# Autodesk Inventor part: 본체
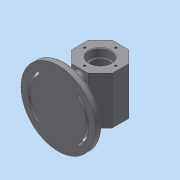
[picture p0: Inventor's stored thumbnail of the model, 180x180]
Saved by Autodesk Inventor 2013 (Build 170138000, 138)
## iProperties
Created: 2017-06
Part Number: 본체
Material: 일반
Document SubType Name: Modeling
Designer: dgall
Density: 1 g/cm^3
Author: dgall
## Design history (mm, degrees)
sketch "스케치1" dims "d0" = 60
  geometry: L1 (12.426, 30)-(30, 12.426); L2 (30, 12.426)-(30, -12.426); L3 (30, -12.426)-(12.426, -30); L4 (12.426, -30)-(-12.426, -30); L5 (-12.426, -30)-(-30, -12.426); L6 (-30, -12.426)-(-30, 12.426); L7 (-30, 12.426)-(-12.426, 30); L8 (-12.426, 30)-(12.426, 30); 4 further points
  constraints: 16 end point, 2 coincident, 2 vertical alignment, 1 midpoint, 19 other
extrude "돌출1" new body sketch "스케치1" stored distance "d1" = 70; taper "d2" = 0 deg
sketch "스케치2"
  geometry: L1 (30, -35)-(-30, -35) reference; L2 (-30, -35)-(-30, 35) reference; L3 (-30, 35)-(30, 35) reference; L4 (30, 35)-(30, -35) reference; L5 (0, -35)-(16, -35); L6 (16, -35)-(16, -23); L7 (16, -23)-(14, -23); L8 (14, -23)-(14, -20); L9 (14, -20)-(25, -20); L10 (25, -20)-(25, 20); L11 (25, 20)-(14, 20); L12 (14, 20)-(14, 23); L13 (14, 23)-(16, 23); L14 (16, 23)-(16, 35); L15 (16, 35)-(0, 35); L16 (0, 35)-(0, -35)
  constraints: 24 end point, 3 horizontal, 3 parallel, 3 perpendicular, 2 collinear, 2 midpoint, 2 point on line, 2 vertical alignment
  dimensions: "d6" = 12 distance of L5.end L6.end; "d7" = 40 distance of L9.end L10.end; "d9" = 12 distance of L13.end L14.end; "d10" = 32 diameter of L14 L16; "d11" = 50 diameter of L10 L16; "d12" = 28 diameter of L12 L16
revolve "회전1" sketch "스케치2" stored, may be unused: angle "d13" = 90 deg
node "작업 평면1"
sketch "스케치3"
  geometry: C1 r 55 at (0, 0); 1 further point
  constraints: 1 centre point, 1 coincident
  dimensions: "d15" = 110 diameter of C1
extrude "돌출2" join sketch "스케치3" distance "d16" = 10; taper "d17" = 0 deg
sketch "스케치4"
  geometry: L1 (-55, 0)-(0, 0); L2 (0, 0)-(-38.891, -38.891); L3 (-30.406, 30.406)-(0, 0); A1 r 55 centre (0, 0) between (-55, 0) and (-38.891, -38.891) reference; A2 r 43 centre (0, 0) between (-30.406, -30.406) and (-30.406, 30.406); A3 r 48 centre (0, 0) between (-33.941, 33.941) and (-33.941, -33.941); A4 r 38 centre (0, 0) between (-26.87, 26.87) and (-26.87, -26.87); A5 r 5 centre (-30.406, -30.406) between (-33.941, -33.941) and (-26.87, -26.87); A6 r 5 centre (-30.406, 30.406) between (-26.87, 26.87) and (-33.941, 33.941)
  constraints: 12 point on circle, 6 end point, 5 centre point, 4 coincident, 3 point on line, 1 horizontal
  dimensions: "d18" = 86 diameter of A2; "d19" = 96 diameter of A3; "d20" = 76 diameter of A4; "d21" = 45 deg angle of L1 L2; "d23" = 90 deg angle of L2 L3
extrude "돌출3" cut sketch "스케치4" distance "d24" = 3; taper "d25" = 0 deg
sketch "스케치5"
  geometry: A1 r 38 centre (0, 0) between (-26.87, 26.87) and (-26.87, -26.87) reference; A2 r 5 centre (-30.406, 30.406) between (-26.87, 26.87) and (-33.941, 33.941) reference; A3 r 48 centre (0, 0) between (-33.941, 33.941) and (-33.941, -33.941) reference; A4 r 5 centre (-30.406, -30.406) between (-33.941, -33.941) and (-26.87, -26.87) reference; A5 r 45 centre (0, 0) between (-31.82, 31.82) and (-31.82, -31.82); A6 r 2 centre (-30.406, 30.406) between (-28.991, 28.991) and (-31.82, 31.82); A7 r 41 centre (0, 0) between (-28.991, 28.991) and (-28.991, -28.991); A8 r 2 centre (-30.406, -30.406) between (-31.82, -31.82) and (-28.991, -28.991)
  constraints: 8 point on circle, 4 centre point, 3 other
  dimensions: "d26" = 3 radial gap between concentric circles of A3 A5
extrude "돌출4" cut sketch "스케치5" stored distance "d27" = 3; taper "d28" = 0 deg
sketch "스케치6"
  geometry: L1 (16, -35)-(16, -23) reference; L2 (16, -23)-(14, -23) reference; L3 (14, -23)-(14, -20) reference; L4 (14, -20)-(25, -20) reference; L5 (25, -20)-(25, 20) reference; L6 (25, 20)-(14, 20) reference; L7 (14, 20)-(14, 23) reference; L8 (14, 23)-(16, 23) reference; L9 (16, 23)-(16, 35) reference; L10 (16, 35)-(30, 35) reference; L11 (30, 35)-(30, -35) reference; L12 (30, -35)-(16, -35) reference; L13 (-16, -23)-(-16, -35) reference; L14 (-16, -35)-(-30, -35) reference; L15 (-30, -35)-(-30, 35) reference; L16 (-30, 35)-(-16, 35) reference; L17 (-16, 35)-(-16, 23) reference; L18 (-16, 23)-(-14, 23) reference; L19 (-14, 23)-(-14, 20) reference; L20 (-14, 20)-(-25, 20) reference; L21 (-25, 20)-(-25, -20) reference; L22 (-25, -20)-(-14, -20) reference; L23 (-14, -20)-(-14, -23) reference; L24 (-14, -23)-(-16, -23) reference; L25 (-62, 55)-(-52, 55) reference; L26 (-52, 55)-(-52, -55) reference; L27 (-52, -55)-(-62, -55) reference; L28 (-62, -55)-(-62, 55) reference; L29 (-30, 29)-(-52, 29); L30 (-30, -29)-(-52, -29); 1 further point
  constraints: 4 end point, 4 point on line, 2 perpendicular
  dimensions: "d29" = 58 distance between parallel lines of L30 L29; "d30" = 29 distance from line of L30 point (0, 0)
extrude "돌출5" join sketch "스케치6" stored distance "d31" = 10; taper "d32" = 0 deg
fillet "모깎기1" dims "d33" = 1
fillet "모깎기2" dims "d34" = 5
fillet "모깎기3" dims "d35" = 5
fillet "모깎기4" dims "d36" = 3
chamfer "모따기1" distance "d37" = 1; stored, may be unused: second distance "d38" = 2, angle "d39" = 45 deg
fillet "모깎기5" dims "d40" = 0.3
fillet "모깎기6" dims "d41" = 3
sketch "스케치7" dims "d42" = 46
  geometry: C1 r 17 at (0, 0) reference; 2 further points
  constraints: 2 vertical alignment, 1 coincident, 2 other
hole "구멍1" sketch "스케치7" at (0, 23) diameter "d43" = 3.242; stored, may be unused: countersink angle "d47" = 90 deg, drill point angle "d49" = 118 deg; dims "d44" = 8, "d45" = 4, "d46" = 2, "d48" = 10
sketch "스케치8"
  geometry: L1 (-24.024, 70)-(0, 70) reference; L2 (0, 0)-(-24.024, 0) reference; C1 r 8 at (-12.012, 35); 2 further points
  constraints: 1 centre point, 1 midpoint, 1 vertical alignment
  dimensions: "d53" = 35 distance from line of L2 C1.centre; "d54" = 16 diameter of C1
extrude "돌출6" join sketch "스케치8" distance "d55" = 7; taper "d56" = 0 deg
sketch "스케치9"
  geometry: C1 r 8 at (0, 0) reference
hole "구멍2" sketch "스케치9" at (0, 0) diameter "d57" = 8; stored, may be unused: countersink angle "d61" = 90 deg, drill point angle "d63" = 118 deg; dims "d58" = 8, "d59" = 4, "d60" = 2, "d62" = 10
chamfer "모따기2" distance "d64" = 1; stored, may be unused: second distance "d65" = 2, angle "d66" = 45 deg
fillet "모깎기7" dims "d67" = 3
sketch "스케치10"
  geometry: L1 (42.012, 0)-(42.012, 70) reference; L2 (24.731, 70)-(41.719, 70) reference; 2 further points
  constraints: 1 other
  dimensions: "d68" = 30 distance from line of point (12.012, 35) L1; "d69" = 35 distance from line of L2 point (12.012, 35)
feature "엠보싱1" sketch "스케치10" dims "d6" = 12, "d7" = 40, "d9" = 12, "d10" = 32, "d11" = 50, "d12" = 28, "d70" = 0.5, "d71" = 0
node "솔리드1"
mirror "대칭1"
pattern_circular "원형 패턴1" dims angle "d51" = 360 deg
mirror "대칭2"
node "절단 모서리 투영1"
node "절단 모서리 투영2"
other parameters: "d14" = -62
